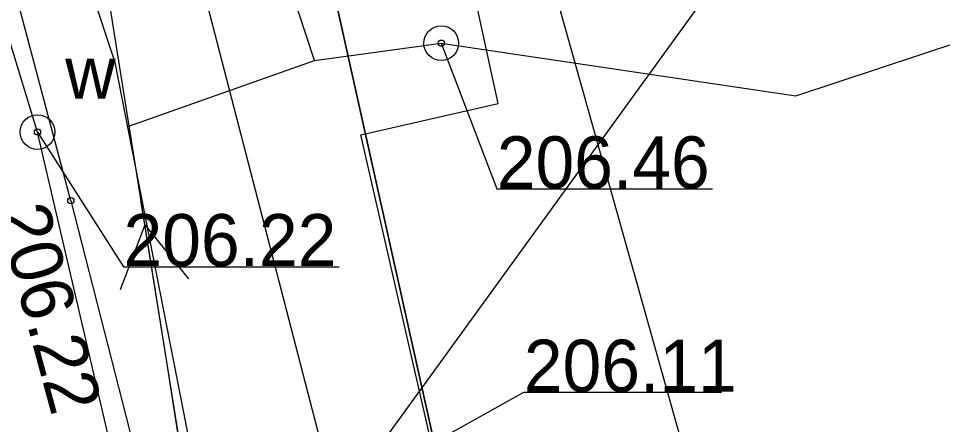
# Model space of a CAD drawing. Extents: x 6512606 to 6513006, y 6022524 to 6022728.
# Drawn here: x 6512859.01 to 6512872.32, y 6022605.01 to 6022610.86 of the extents above; entities that cross this region are included whole.
import ezdxf

# ---------------------------------------------------------------- set-up
doc = ezdxf.new("R2010")
doc.units = 0
for name, color, linetype in [('217-kontur klasyfikacyjny', 7, 'Continuous'), ('218-kontur użytku gruntowego', 7, 'Continuous'), ('219-działka ewidencyjna', 7, 'Continuous'), ('4', 7, 'Continuous'), ('budynek projektowany (powierzchnia)', 7, 'Continuous'), ('Default', 7, 'Continuous'), ('krawężnik (linia)', 7, 'Continuous'), ('maxp_opisy', 7, 'Continuous'), ('Obszar opracowania', 7, 'Continuous'), ('przewód elektroenergetyczny niskiego napięcia (linia)', 7, 'Continuous'), ('przewód elektroenergetyczny niskiego napięcia (linia) - symbol', 7, 'Continuous'), ('przewód gazowy (linia)', 7, 'Continuous'), ('przewód wodociągowy (linia)', 7, 'Continuous'), ('punkt o określonej wysokości (sieć wodociągowa)', 7, 'Continuous'), ('punkt o określonej wysokości (sieć wodociągowa)-Atr2', 7, 'Continuous'), ('punkt wysokościowy sztuczny', 7, 'Continuous'), ('punkt wysokościowy sztuczny-Atr2', 7, 'Continuous'), ('właz okrągły - siec wodociągowa (punkt)', 7, 'Continuous'), ('właz okrągły - siec wodociągowa (punkt)-Atr17', 7, 'Continuous')]:
    doc.layers.add(name, color=color, linetype=linetype)

# ---------------------------------------------------------------- blocks, each defined once
blk = doc.blocks.new('US22')
at = {"layer": 'Default'}
blk.add_circle((0, 0), 2.5, dxfattribs=at)
blk = doc.blocks.new('PW01')
at = {"layer": 'Default'}
blk.add_circle((0, 0), 0.45, dxfattribs=at)
blk = doc.blocks.new('PE04')
at = {"layer": 'Default'}
for p, q in [((46.5, 0), (37.84, 5)), ((6.5, 0), (0, 0)), ((6.5, 0), (16.5, 0)), ((16.5, 0), (26.5, 0)), ((26.5, 0), (36.5, 0)), ((36.5, 0), (46.5, 0)), ((46.5, 0), (37.84, -5)), ((46.5, 0), (50, 0))]:
    blk.add_line(p, q, dxfattribs=at)
blk = doc.blocks.new('PW02')
at = {"layer": 'Default'}
blk.add_circle((0, 0), 0.45, dxfattribs=at)

msp = doc.modelspace()

# ---------------------------------------------------------------- linework, layer by layer
at = {"layer": '217-kontur klasyfikacyjny'}
msp.add_lwpolyline([(6512862.63, 6022615.38), (6512866.69, 6022597.16)], dxfattribs=at)
at = {"layer": '218-kontur użytku gruntowego'}
for points in [[(6512862.63, 6022615.38), (6512866.69, 6022597.16)], [(6512866.69, 6022597.16), (6512862.63, 6022615.38)]]:
    msp.add_lwpolyline(points, dxfattribs=at)
at = {"layer": '219-działka ewidencyjna'}
msp.add_lwpolyline([(6512866.69, 6022597.16), (6512862.63, 6022615.38)], dxfattribs=at)
at = {"layer": '4'}
msp.add_lwpolyline([(6512866.69, 6022597.16), (6512862.63, 6022615.38)], dxfattribs=at)
at = {"layer": 'budynek projektowany (powierzchnia)'}
msp.add_lwpolyline([(6512876.905, 6022604.629), (6512866.3, 6022602.19), (6512866.5, 6022601.27), (6512865.79, 6022601.1), (6512863.94, 6022609.18), (6512865.92, 6022609.63), (6512865.01, 6022613.81), (6512862.96, 6022613.3), (6512860.72, 6022623.09)], dxfattribs=at)
at = {"layer": 'krawężnik (linia)'}
for points in [[(6512859.76, 6022608.23), (6512858.81, 6022611.81), (6512856.05, 6022621.44), (6512855.08, 6022624.94), (6512854.44, 6022627.77)], [(6512859.76, 6022608.23), (6512861.41, 6022601.79)]]:
    msp.add_lwpolyline(points, dxfattribs=at)
at = {"layer": 'maxp_opisy'}
msp.add_lwpolyline([(6512856.121, 6022593.53), (6512879.345, 6022625.572), (6512868.61, 6022653.292)], dxfattribs=at)
at = {"layer": 'Obszar opracowania'}
msp.add_lwpolyline([(6512710.98, 6022693.84), (6512748.35, 6022694.16), (6512798.11, 6022695.25), (6512807.47, 6022695.46), (6512809.66, 6022606.87), (6512863.71, 6022622.03), (6512875.13, 6022581.36), (6512755.22, 6022535.25), (6512691.61, 6022568.03), (6512709.16, 6022605.16)], close=True, dxfattribs=at)
at = {"layer": 'przewód elektroenergetyczny niskiego napięcia (linia)'}
msp.add_lwpolyline([(6512861.56, 6022603.29), (6512856.13, 6022637.29)], dxfattribs=at)
at = {"layer": 'przewód gazowy (linia)'}
msp.add_lwpolyline([(6512871.862, 6022571.535), (6512870.29, 6022578.43), (6512869.58, 6022581.52), (6512865.64, 6022595.96), (6512860.06, 6022617.51), (6512858.39, 6022625.33), (6512855.49, 6022634.19), (6512854.83, 6022641.62)], dxfattribs=at)
at = {"layer": 'przewód wodociągowy (linia)'}
for points in [[(6512861.84, 6022602.88), (6512860.4, 6022610.22), (6512855.52, 6022624.92), (6512854.13, 6022628.72), (6512853.02, 6022630.73), (6512851.7, 6022633.1), (6512848.7, 6022639.72)], [(6512863.27, 6022610.25), (6512857.52, 6022627.72)], [(6512859.28, 6022609.22), (6512855.66, 6022621.07)], [(6512865.1, 6022610.5), (6512870.21, 6022609.74), (6512875.021, 6022611.337)], [(6512860.58, 6022609.3), (6512863.27, 6022610.25), (6512865.1, 6022610.5)], [(6512860.86, 6022602.44), (6512859.28, 6022609.22)]]:
    msp.add_lwpolyline(points, dxfattribs=at)
at = {"layer": 'punkt o określonej wysokości (sieć wodociągowa)-Atr2'}
for points in [[(6512865.1, 6022610.5), (6512865.9, 6022608.4), (6512869.009, 6022608.4)], [(6512859.28, 6022609.22), (6512860.52, 6022607.28), (6512863.629, 6022607.28)], [(6512860.86, 6022602.44), (6512866.29, 6022605.47), (6512869.138, 6022605.47)]]:
    msp.add_lwpolyline(points, dxfattribs=at)

# ---------------------------------------------------------------- block references
at = {"layer": 'przewód elektroenergetyczny niskiego napięcia (linia) - symbol', "xscale": 0.09999999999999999, "yscale": 0.1, "rotation": 99.074}
msp.add_blockref('PE04', (6512861.56, 6022603.29), dxfattribs=at)
at = {"layer": 'punkt o określonej wysokości (sieć wodociągowa)', "xscale": 0.1, "yscale": 0.10000000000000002, "rotation": 17.811999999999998}
msp.add_blockref('PW01', (6512865.1, 6022610.5), dxfattribs=at)
at = {"layer": 'punkt o określonej wysokości (sieć wodociągowa)', "xscale": 0.1, "yscale": 0.10000000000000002}
msp.add_blockref('PW01', (6512859.28, 6022609.22), dxfattribs=at)
at = {"layer": 'punkt wysokościowy sztuczny', "xscale": 0.1, "yscale": 0.10000000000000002}
msp.add_blockref('PW02', (6512859.76, 6022608.23), dxfattribs=at)
at = {"layer": 'właz okrągły - siec wodociągowa (punkt)', "xscale": 0.1, "yscale": 0.10000000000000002, "rotation": 17.811999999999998}
msp.add_blockref('US22', (6512865.1, 6022610.5), dxfattribs=at)
at = {"layer": 'właz okrągły - siec wodociągowa (punkt)', "xscale": 0.1, "yscale": 0.10000000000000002}
msp.add_blockref('US22', (6512859.28, 6022609.22), dxfattribs=at)

# ---------------------------------------------------------------- texts
at = {"layer": 'punkt o określonej wysokości (sieć wodociągowa)-Atr2'}
for s, p in [('206.46', (6512865.9, 6022608.408)), ('206.22', (6512860.52, 6022607.288)), ('206.11', (6512866.29, 6022605.478))]:
    msp.add_text(s, height=0.75, dxfattribs=at).set_placement(p)
at = {"layer": 'punkt wysokościowy sztuczny-Atr2'}
msp.add_text('206.22', height=0.75, rotation=285.164, dxfattribs=at).set_placement((6512858.69, 6022608.07))
at = {"layer": 'właz okrągły - siec wodociągowa (punkt)-Atr17'}
msp.add_text('w', height=0.75, dxfattribs=at).set_placement((6512859.68, 6022609.7))

doc.saveas('drawing.dxf')
